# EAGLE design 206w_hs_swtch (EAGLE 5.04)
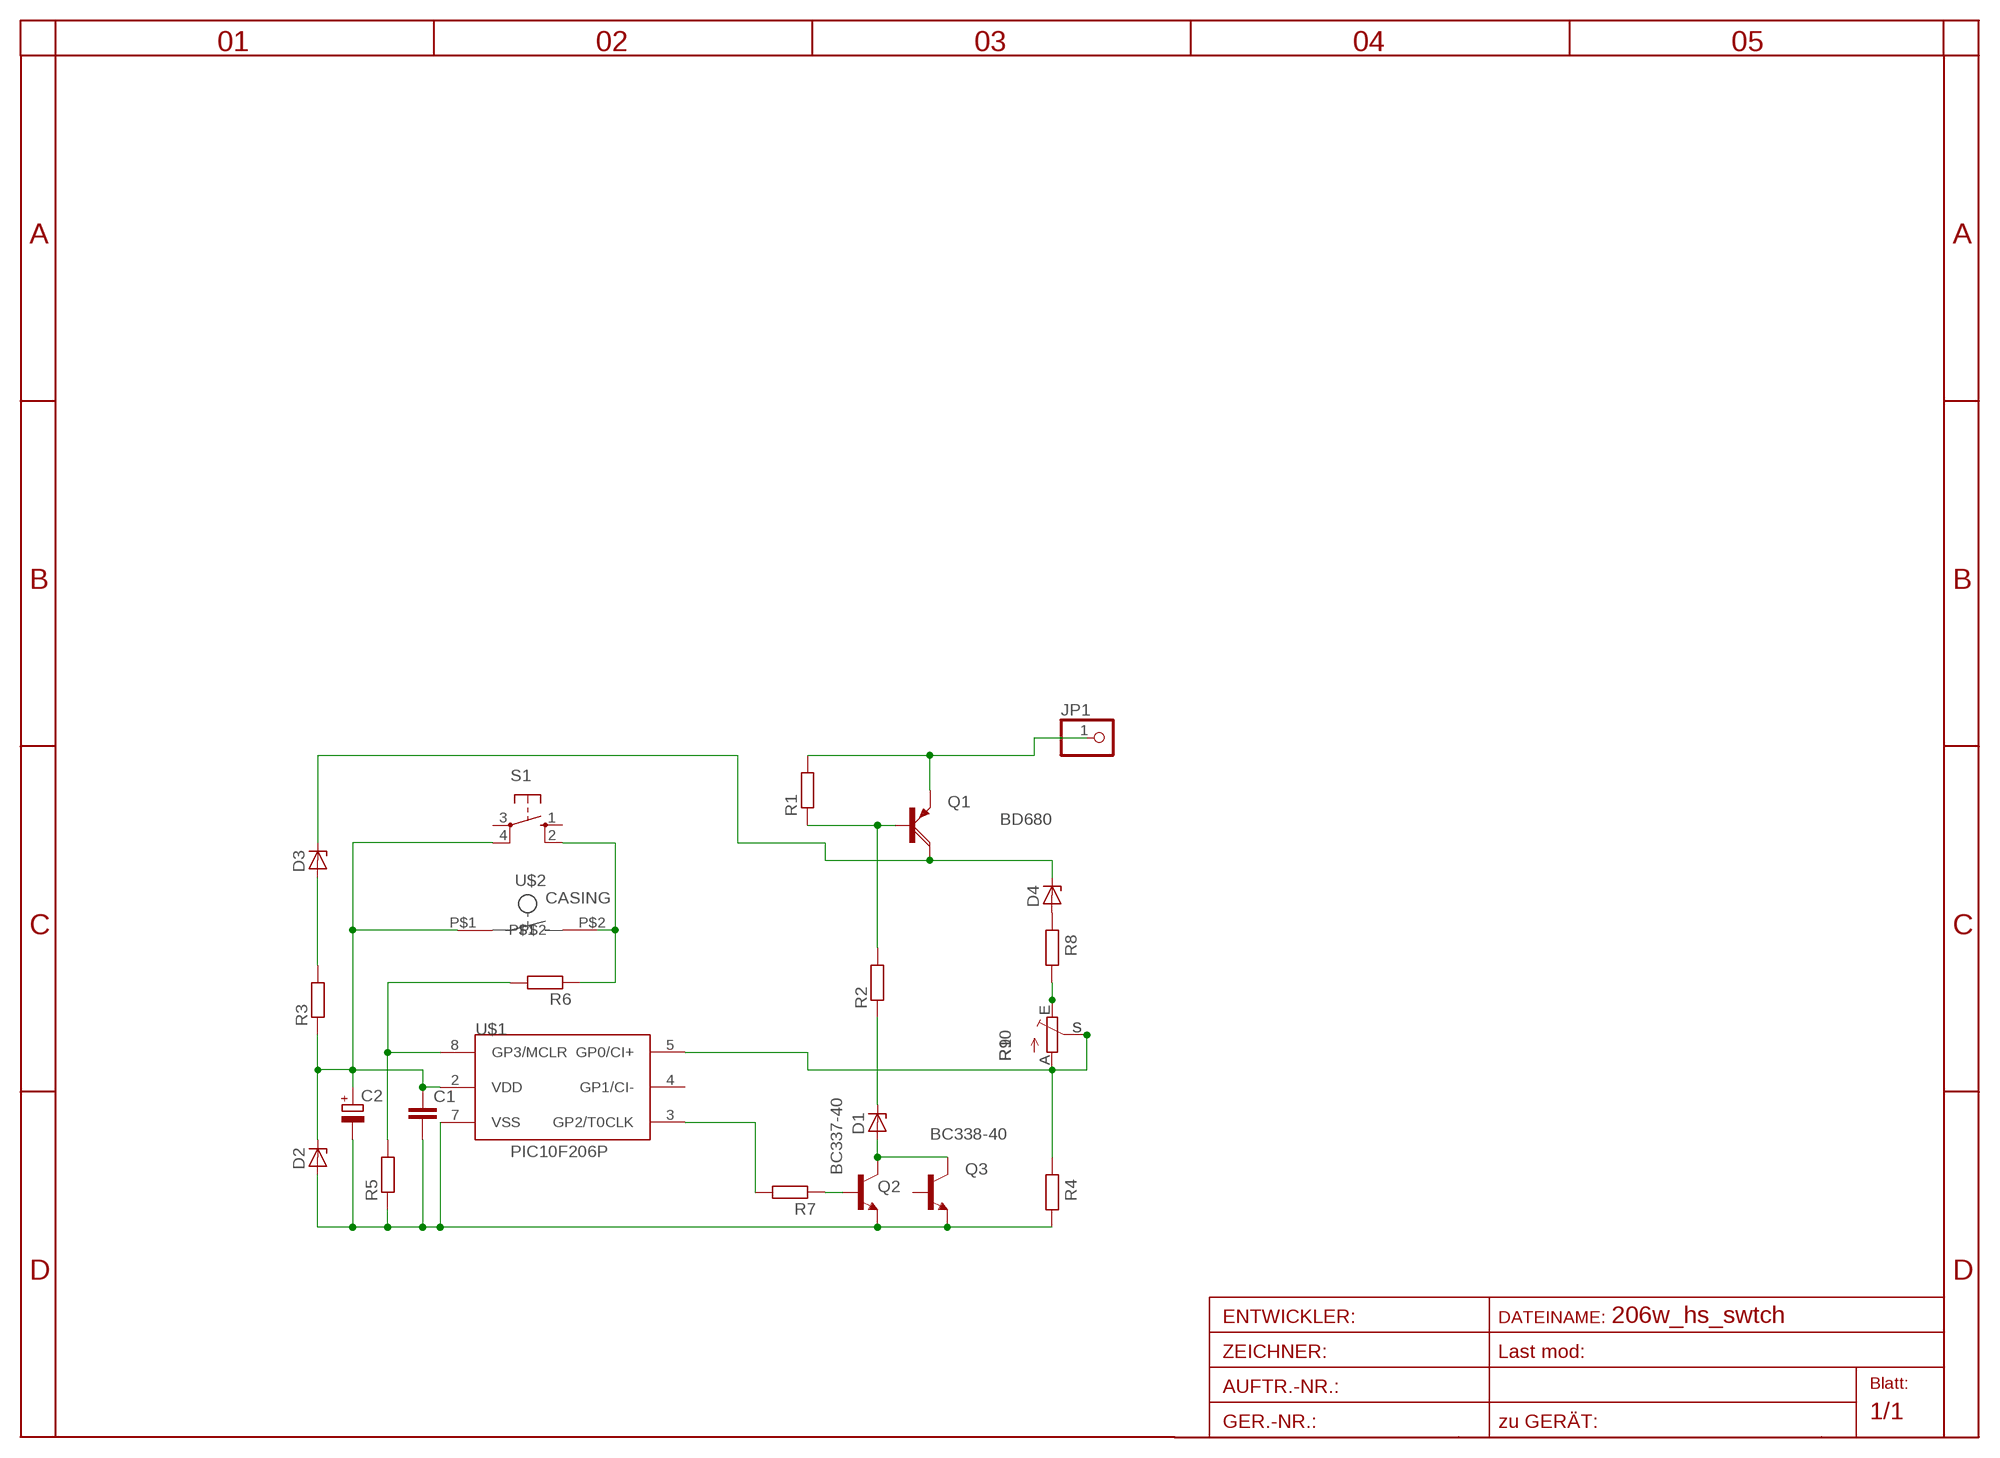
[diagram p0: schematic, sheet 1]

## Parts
C1  C-EU025-025X050  [C025-025X050]
C2  CPOL-EUE2.5-5  [E2,5-5]
D1  ZENER-DIODEDO41-20  [DO41-20]
D2  ZENER-DIODEZD-7.5  [ZDIO-7.5]
D3  ZENER-DIODEZD-7.5  [ZDIO-7.5]
D4  ZENER-DIODEZD-10  [ZDIO-10]
JP1  PINHD-1X1  [1X01]
Q1  BD680  [TO126AV]
Q2  BC337-40  [TO92]
Q3  BC338-40  [TO92-EBC]
R1  R-EU_0207/10  [0207/10]
R2  R-EU_0204/7  [0204/7]
R3  R-EU_0204/7  [0204/7]
R4  R-EU_0204/7  [0204/7]
R5  R-EU_0204/7  [0204/7]
R6  R-EU_0204/7  [0204/7]
R7  R-EU_0204/7  [0204/7]
R8  R-EU_0207/10  [0207/10]
R9  TRIM_EU-CA6V  [CA6V]
R10  TRIM_EU-LI15  [LI15]
S1  10-XX  [B3F-10XX]
U$1  PIC10F206P  [DIL8]
U$2  CASING  [CASING]

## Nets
GND: C1.2 C2.- D2.A Q2.1(E) Q3.E R4.1 R5.1 U$1.7(VSS)
N$1: D4.A R8.2
N$2: C1.1 C2.+ D2.C R3.1 S1.4(P1) U$1.2(VDD) U$2.P$1
N$3: D3.A R3.2
N$5: R5.2 R6.2 U$1.8(GP3/MCLR)
N$7: R6.1 S1.2(S1) U$2.P$2
N$8: R4.2 R9.A R9.S R10.A R10.S U$1.5(GP0/CI+)
N$9: R7.2 U$1.3(GP2/T0CLK)
N$10: Q2.2(B) R7.1
N$11: D1.A Q2.3(C) Q3.C
N$12: D1.C R2.1
N$13: Q1.B R1.1 R2.2
N$15: R8.1 R9.E R10.E
N$17: JP1.1 Q1.E R1.2
V60: D3.C D4.C Q1.C
Unconnected: Q3.B S1.1(S) S1.3(P) U$1.4(GP1/CI-)

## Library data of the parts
C1 = rcl:C-EU: CAPACITOR, European symbol
C2 = rcl:CPOL-EU: POLARIZED CAPACITOR, European symbol
D1-D4 = diode-1:ZENER-DIODE: Z-Diode
JP1 = pinhead:PINHD-1X1: PIN HEADER
Q1 = transistor-power:BD680: PNP DARLINGTON TRANSISTOR
Q2 = transistor-npn:BC337*: NPN Transistor
Q3 = transistor-npn:BC338*: NPN Transistor
R1-R8 = rcl:R-EU_: RESISTOR, European symbol
R9 R10 = pot:TRIM_EU-: POTENTIOMETER
S1 = switch-omron:10-XX: OMRON SWITCH
U$1 = microchip-5:PIC10F2*: uPC nW 0,25/0,5k Program Flash memory Comparator
U$2 = button:CASING

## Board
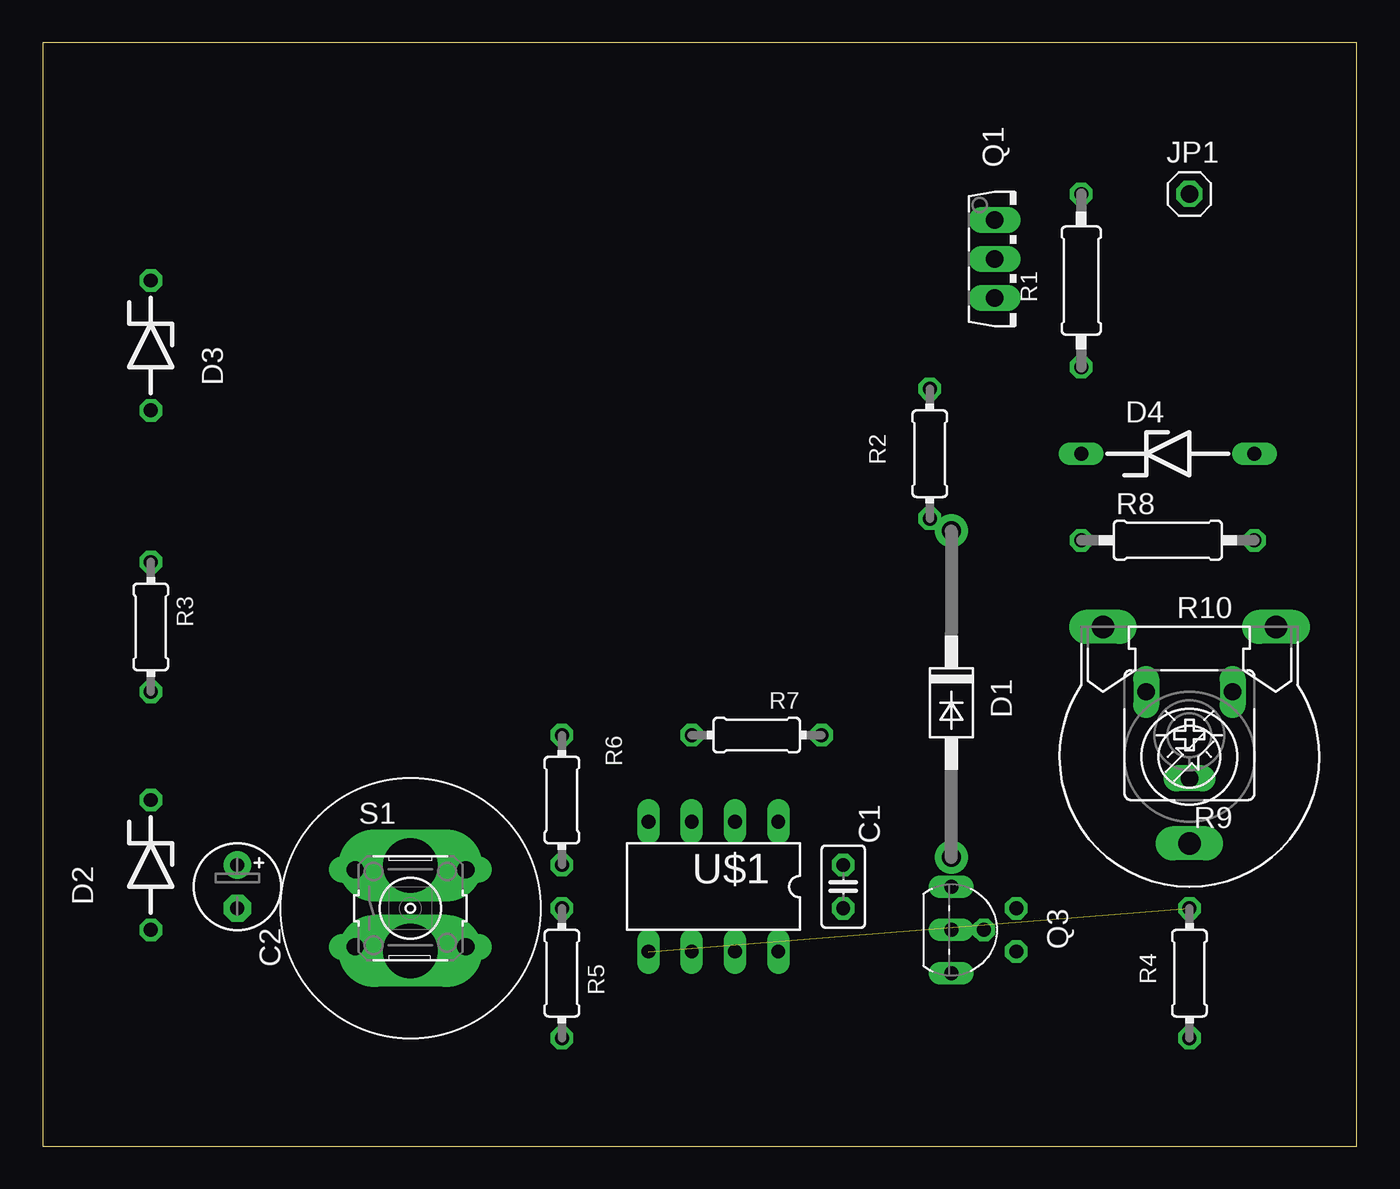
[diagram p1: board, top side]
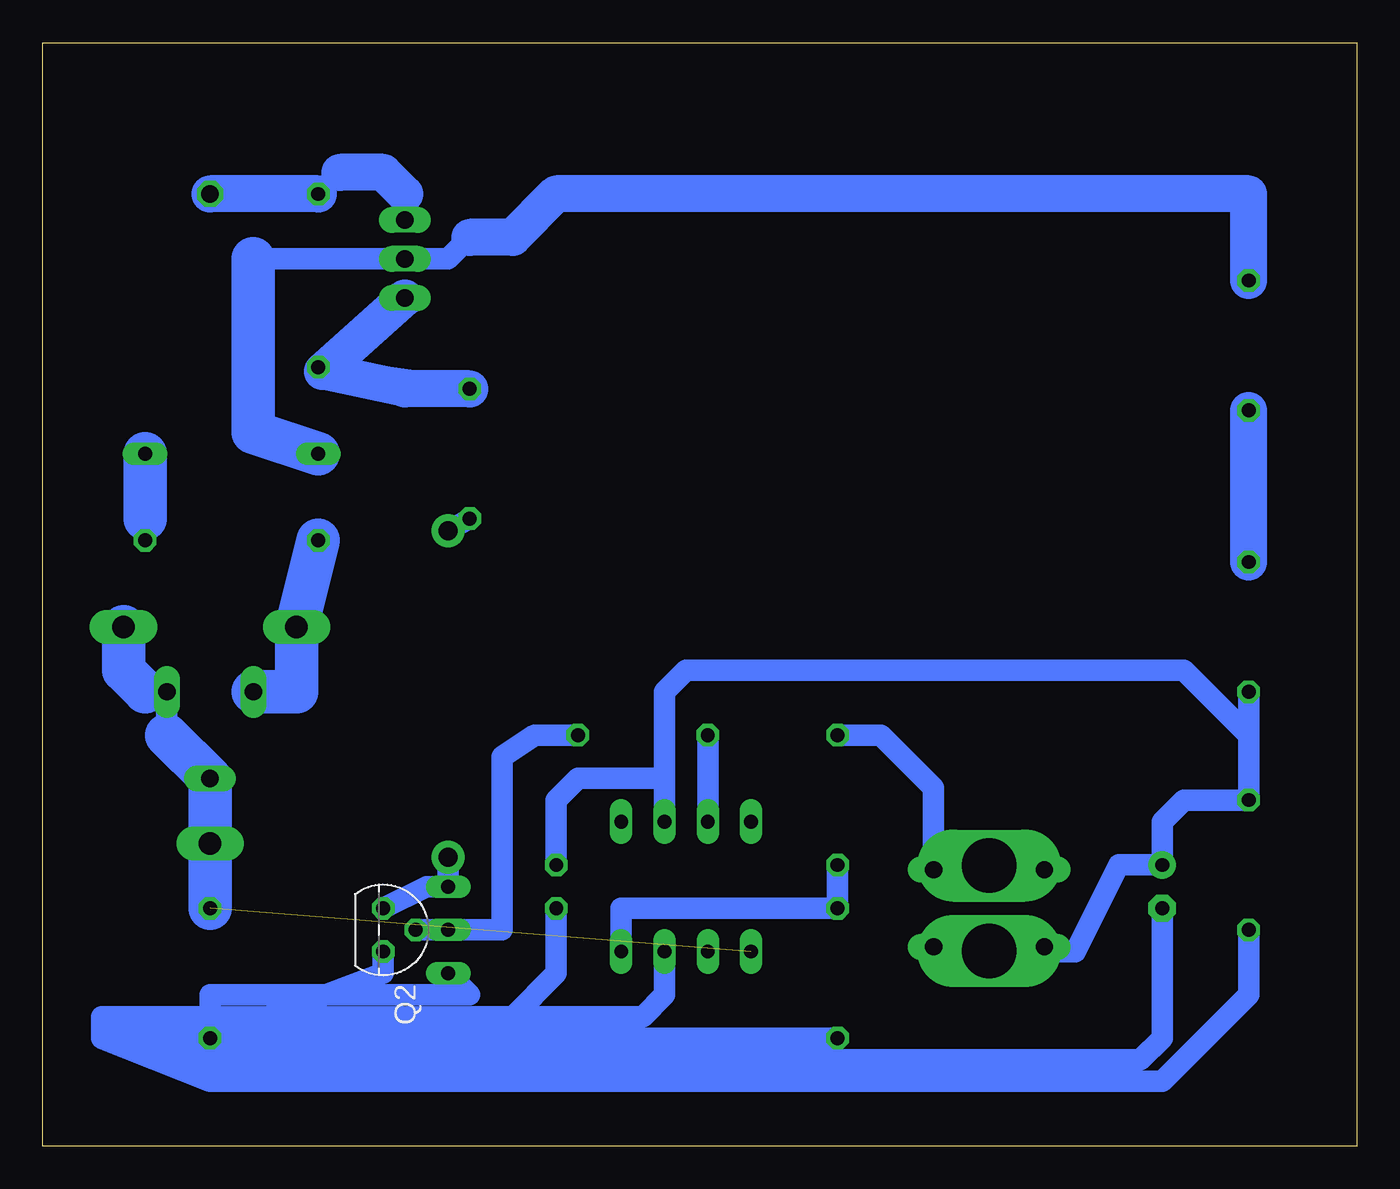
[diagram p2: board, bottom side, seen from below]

Size 77.14 x 64.76 mm. Coordinates in mm from the lower left corner, seen from the top.
Outline: 0,0 77.14,0 77.14,64.76 0,64.76 0,0
Copper layers (1*16): Top 0.035mm / dielectric 1.5mm / Bottom 0.035mm
Design rules "default": minimum track width 10mil, minimum drill 24mil, track to track 8mil, track to pad 8mil, pad to pad 8mil, via to via 8mil, smd to smd 8mil, copper to edge 40mil, drill to drill 8mil, minimum pad ring 10mil, minimum via ring 8mil, stop-mask expansion 4mil, vias tented up to drill 0mil, thermal gap 10mil

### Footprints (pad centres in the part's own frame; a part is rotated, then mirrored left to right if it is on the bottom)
C025-025X050 = drill 0.813 octagon: 1 -1.27,0; 2 1.27,0
E2,5-5 = drill 0.813 pad 1.6 round: + -1.27,0 | drill 0.813 pad 1.6 octagon: - 1.27,0
DO41-20 = drill 1.118 pad 1.93 round: A 9.08,0; C -10.08,0
ZDIO-7.5 = drill 0.813 octagon: A 3.81,0; C -3.81,0
ZDIO-10 = drill 0.813 long: A 5.08,0; C -5.08,0
1X01 = drill 1.016 octagon: 1 0,0
TO126AV = drill 1.016 long: B 2.286,-1.27; C 0,-1.27; E -2.286,-1.27
TO92 = drill 0.813 octagon: 1 1.27,0; 2 0,1.905; 3 -1.27,0
TO92-EBC = drill 0.813 long: B 0,-1.27; C -2.54,-1.27; E 2.54,-1.27
0207/10 = drill 0.813 octagon: 1 -5.08,0; 2 5.08,0
0204/7 = drill 0.813 octagon: 1 -3.81,0; 2 3.81,0
CA6V = drill 1.016 long: A -2.54,-2.54; E 2.54,-2.54; S 0,2.54
LI15 = drill 1.321 long: A -5.08,-7.62; E 5.08,-7.62; S 0,5.08
B3F-10XX = drill 1.016 long: 1 -3.251,2.261; 2 3.251,2.261; 3 -3.251,-2.261; 4 3.251,-2.261
DIL8 = drill 0.813 long: 1 -3.81,-3.81; 2 -1.27,-3.81; 3 1.27,-3.81; 4 3.81,-3.81; 5 3.81,3.81; 6 1.27,3.81; 7 -1.27,3.81; 8 -3.81,3.81
CASING = drill 3.2 pad 3.81 long: P$1 -2.5,0; P$2 2.5,0

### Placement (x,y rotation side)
C1  46.99,15.24 270 top
C2  11.43,15.24 270 top
D1  53.34,26.04 270 top
D2  6.35,16.51 270 top
D3  6.35,46.99 270 top
D4  66.04,40.64 0 top
JP1  67.31,55.88 0 top
Q1  57.15,52.07 270 top
Q2  57.15,12.7 270 bottom
Q3  54.61,12.7 270 top
R1  60.96,50.8 90 top
R2  52.07,40.64 90 top
R3  6.35,30.48 90 top
R4  67.31,10.16 90 top
R5  30.48,10.16 90 top
R6  30.48,20.32 270 top
R7  41.91,24.13 180 top
R8  66.04,35.56 0 top
R9  67.31,24.13 180 top
R10  67.31,22.86 180 top
S1  21.59,13.97 0 top
U$1  39.37,15.24 180 top
U$2  21.59,13.97 90 top

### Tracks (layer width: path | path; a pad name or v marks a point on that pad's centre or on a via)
GND
  Bottom 1.27: D2.A 6.35,8.89 11.43,3.81 67.31,3.81 73.66,6.35 73.66,7.62 | 73.66,7.62 R4.1 | R4.1 57.15,10.16 Q2.1 | C2.- 11.43,6.35 12.7,5.08 67.31,5.08 73.66,7.62 | 73.66,7.62 68.58,6.35 R5.1 | U$1.7 40.64,8.89 41.91,7.62 49.53,7.62 | 73.66,7.62 49.53,7.62 | Q3.E 52.07,8.89 67.31,8.89 R4.1 | C1.2 46.99,10.16 49.53,7.62
N$1
  Bottom 0.406: 71.12,36.83 R8.2
  Bottom 2.54: D4.A 71.12,36.83
N$2
  Bottom 1.27: 24.56,11.43 16.51,11.43 13.97,16.51 C2.+ 11.43,19.05 10.16,20.32 D2.C 6.35,24.13 | 24.56,11.43 S1.4 | 24.56,11.43 21.63,11.43 U$2.P$1 | 40.64,21.59 40.64,26.67 39.37,27.94 10.16,27.94 6.35,24.13 | 40.64,21.59 U$1.2 | C1.1 46.99,20.32 45.72,21.59 40.64,21.59 | 6.35,24.13 R3.1
N$3
  Bottom 2.184: R3.2 D3.A
N$5
  Bottom 1.27: U$1.8 43.18,13.97 R5.2 R6.2
N$7
  Bottom 1.27: R6.1 27.94,24.13 24.84,21.03 S1.2 21.83,16.23 U$2.P$2
N$8  (1 unrouted)
  Bottom 1.27: 71.12,26.67 R9.A 69.85,24.13
  Bottom 2.54: R10.A 72.39,27.94 71.12,26.67 | 69.85,24.13 R9.S R10.S R4.2
N$9
  Bottom 1.27: U$1.3 R7.2
N$10
  Bottom 1.27: R7.1 48.26,24.13 50.16,22.86 50.16,12.7 Q2.2
N$11
  Bottom 1.27: Q2.3 54.61,15.24 Q3.C D1.A
N$12
  Bottom 1.27: R2.1 D1.C
N$13
  Bottom 1.27: R2.2 R1.1
  Bottom 2.184: Q1.B 60.71,45.47 55.88,44.45 R2.2
N$15
  Bottom 2.54: R8.1 R10.E 62.23,26.67 R9.E
N$17
  Bottom 1.27: Q1.E 55.88,55.88 | 59.69,57.15 R1.2
  Bottom 2.184: R1.2 JP1.1 | 55.88,55.88 57.15,57.15 59.69,57.15
V60
  Bottom 1.27: 52.07,53.34 53.34,52.07 Q1.C 64.77,52.07
  Bottom 2.184: D3.C 6.35,55.88 46.99,55.88 49.53,53.34 52.07,53.34
  Bottom 2.54: 64.77,52.07 64.77,41.91 D4.C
